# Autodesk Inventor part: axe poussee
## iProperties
Created: 2002-03
Part Number: axe poussee
Material: Par défaut
Document SubType Name: Modélisation
Designer: BAVERGE
Control State: 0
Master: False
Checked Out: False
Shininess: 60.0
Length Units: 11269
Angle Units: 11279
Time Units: 11290
Mass Units: 11283
Length Display Precision: 3
Angle Display Precision: 2
Density: 0.0
Volumn: 0.0
Area: 0.0
PropertySet Name: Model Information
Author: BAVERGE
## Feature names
1. Révolution1 [Revolution]
